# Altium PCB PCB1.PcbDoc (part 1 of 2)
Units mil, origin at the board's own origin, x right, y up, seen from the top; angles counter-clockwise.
Board outline 3937.01 x 3937.01 mil, 2 copper layers (Top Layer, Bottom Layer), stack 65.792 mil thick; 127 components, 100 nets, 530 pads, 138 vias.
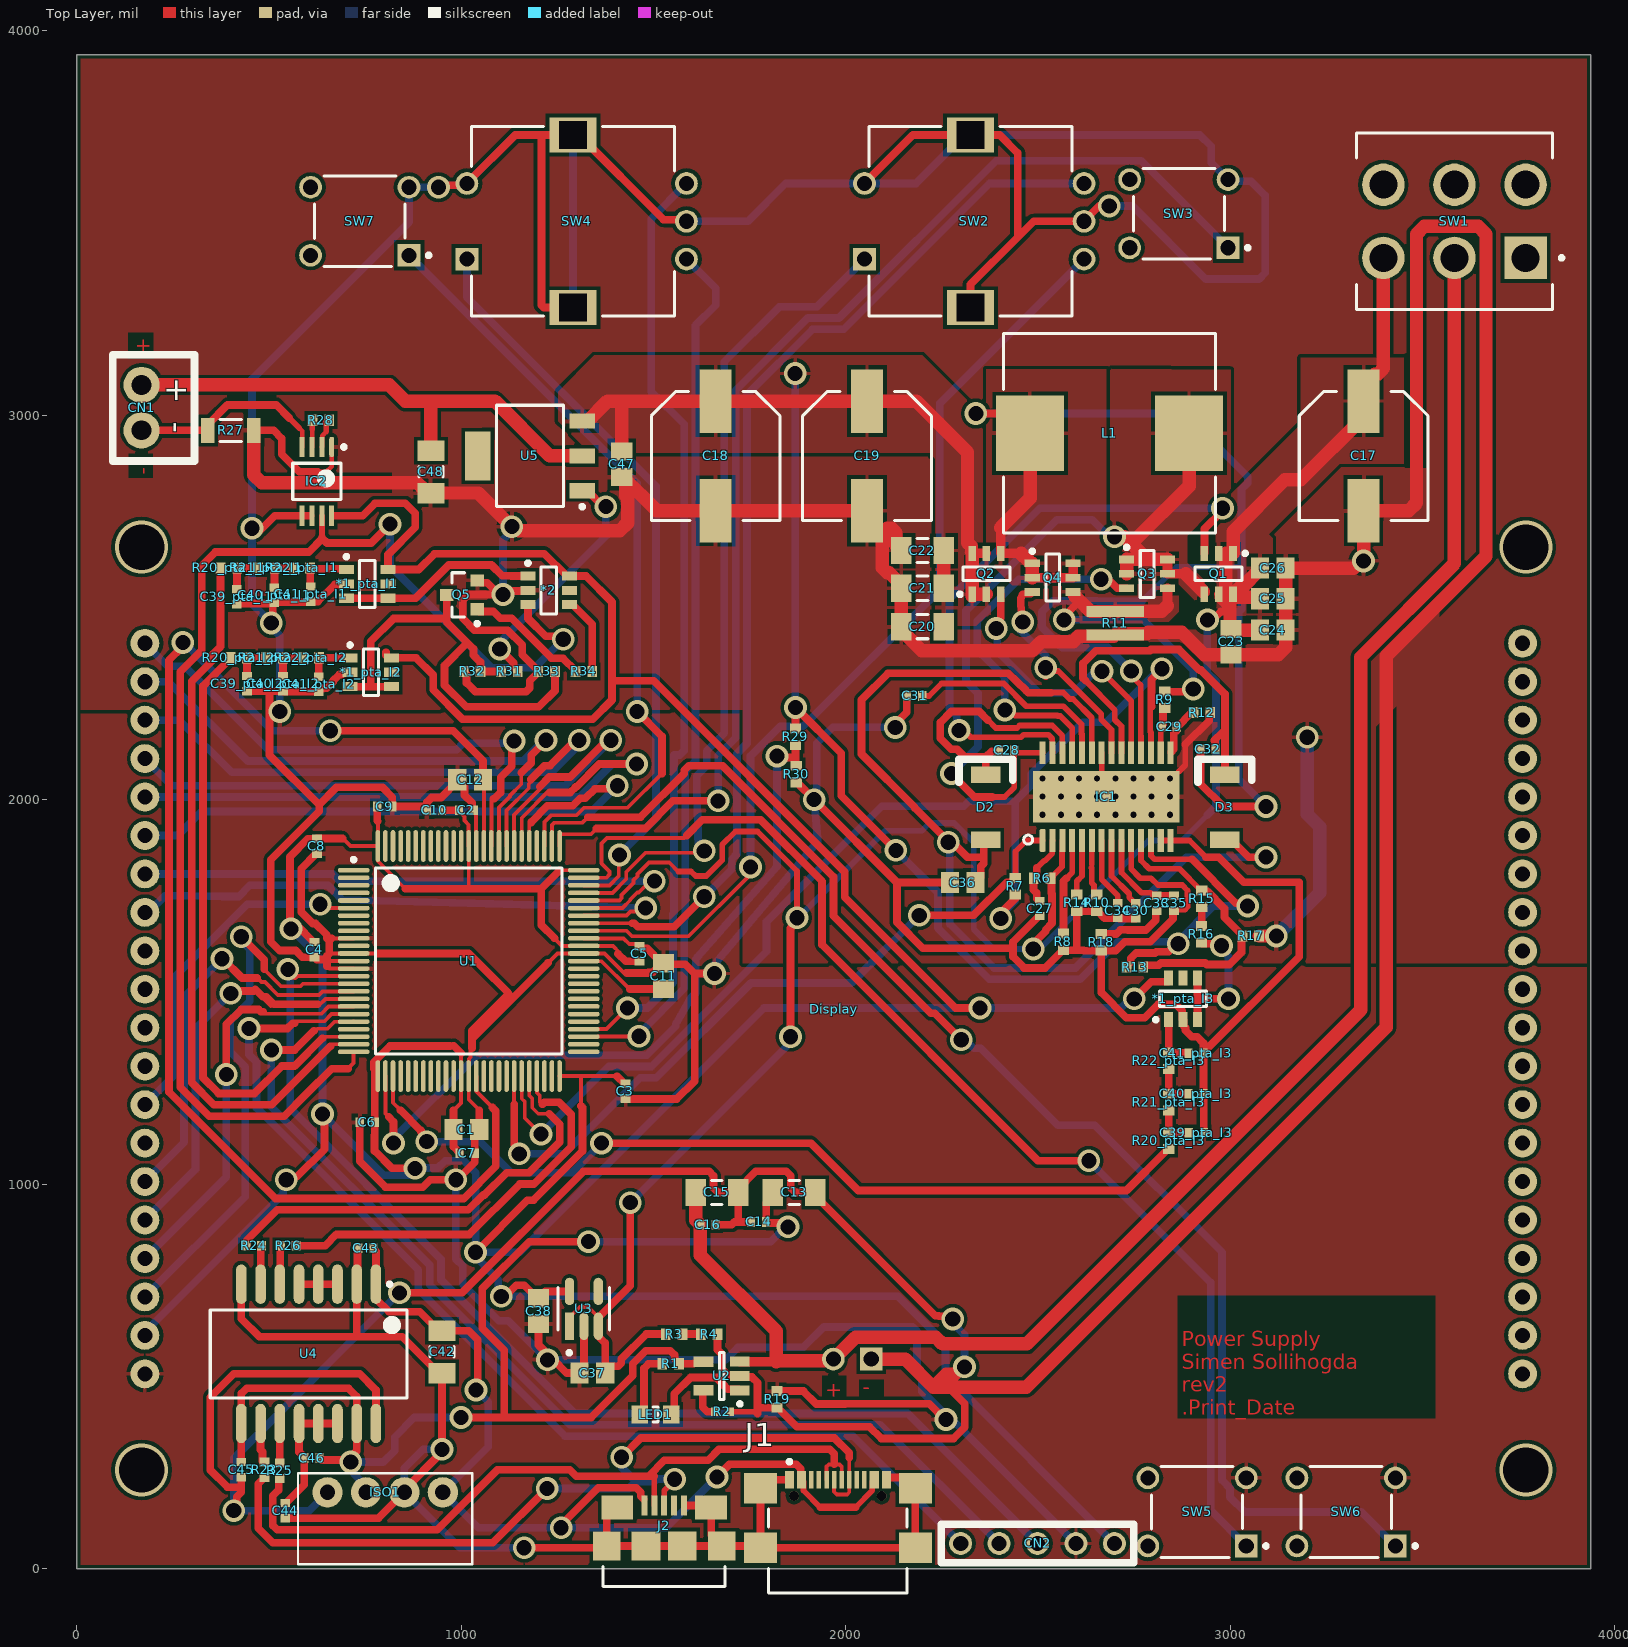
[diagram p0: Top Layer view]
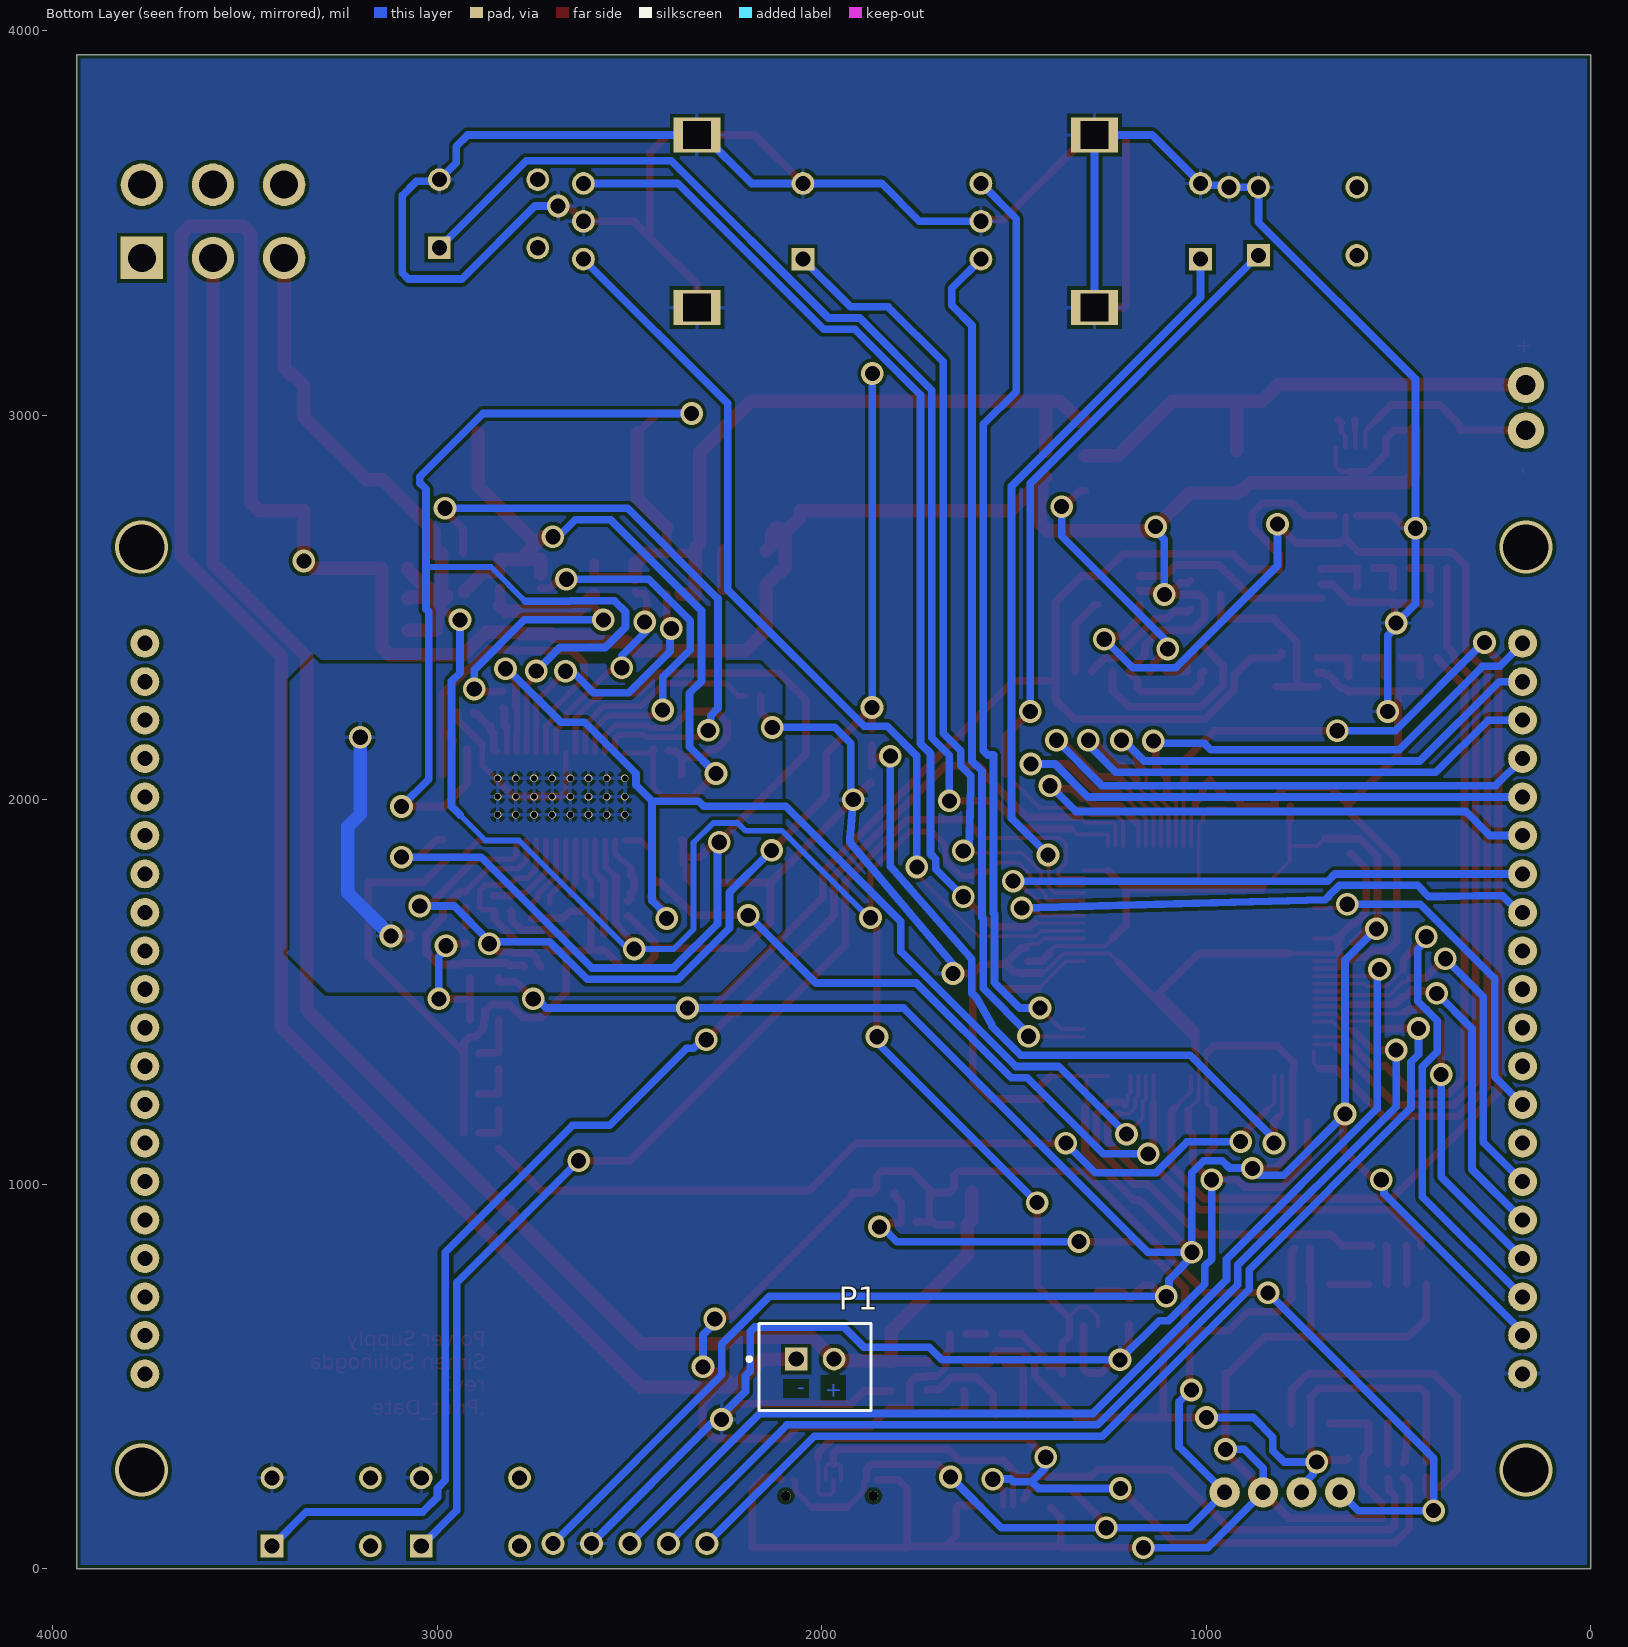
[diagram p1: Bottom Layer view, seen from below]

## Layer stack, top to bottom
Top Solder: solder mask 0.4, Solder Resist, Dk 3.5
Top Layer: signal copper 1.4
Dielectric 1: dielectric 62.9921, FR-4, Dk 4.8
Bottom Layer: signal copper 1.4
Bottom Solder: solder mask 0.4, Solder Resist, Dk 3.5

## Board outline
0,0 3937.01,0 3937.01,3937.01 0,3937.01

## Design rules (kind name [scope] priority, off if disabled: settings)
BoardOutlineClearance [(OnLayer('Bottom Layer') OR OnLayer('Top Layer') ) and not InAnyComponent] p1: gap=10 ignorepadtopadclearanceinfootprint=FALSE except(0: Arc-SplitContinuation Track-SplitContinuation SMDPad-SplitContinuation THPad-SplitContinuation Via-SplitContinuation Fill-SplitContinuation Poly-SplitContinuation Region-SplitContinuation Text-SplitContinuation; 39.37: Track-OutlineEdge SMDPad-OutlineEdge THPad-OutlineEdge Via-OutlineEdge; 118.11: Text-OutlineEdge)
Clearance Clearance_2 [InComponent('u1') or InComponent('J1') vs IsWire] p1: gap=6 ignorepadtopadclearanceinfootprint=FALSE
Clearance Clearance_1 [IsPad vs IsPad] p2: gap=6 ignorepadtopadclearanceinfootprint=FALSE
Clearance [All] p3: gap=9.5 ignorepadtopadclearanceinfootprint=FALSE
HoleSize HoleSize_1 [InComponent('IC1') or InComponent('J1')] p1: absolutevalues=TRUE maxlimit=100 minlimit=11.81 maxpercent=80.000 minpercent=20.000
HoleSize [All] p2: absolutevalues=TRUE maxlimit=2362.2 minlimit=31.5 maxpercent=80.000 minpercent=20.000
MinimumSolderMaskSliver [not InAnyComponent] p1: minsoldermaskwidth=4
PolygonConnect [All] p1: connectstyle=Relief reliefconductorwidth=10 reliefentries=4 polygonreliefangle="90 Angle" airgapwidth=10
RoutingVias [All] p1: holewidth=15.75 width=22.05 viastyle="Through Hole" minholewidth=15.75 minwidth=22.05 maxholewidth=39.37 maxwidth=78.74
SilkToSilkClearance [All] p1 off: silktosilkclearance=10
SilkToSolderMaskClearance [IsPad] p1: minsilkscreentomaskgap=0 clearancetoexposedcopper=FALSE
SolderMaskExpansion [All] p1: expansion=4 istentingtop=FALSE
Width [All] p1: maxlimit=100 minlimit=8 preferedwidth=20
26 further rules are at their usual default settings.

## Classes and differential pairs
component class U_programmer: CN2
component class U_linear_regulator: *2 C47 C48 Q5 R31 R32 R33 R34 U5
component class U_Display: Display
component class pta_I1: *1_pta_I1 C39_pta_I1 C40_pta_I1 C41_pta_I1 R20_pta_I1 R21_pta_I1 R22_pta_I1
component class U_Driver: CN1 R29 R30
component class U_mcu: C1 C2 C3 C4 C5 C6 C7 C8 C9 C10 C11 C12 U1
component class U_knobs: SW2 SW3 SW4 SW5 SW6 SW7
component class U_current_sense: IC2 R27 R28
component class U_Booster: C17 C18 C19 C20 C21 C22 C23 C24 C25 C26 C27 C28 C29 C30 C31 C32 C33 C34 C35 C36 D2 D3 IC1 L1 Q1 Q2 Q3 Q4 R6 R7 R8 R8_U_Booster R9 R10 R11 R12 R13 R14 R15 R16 R17 R18
component class pta_I3: *1_pta_I3 C39_pta_I3 C40_pta_I3 C41_pta_I3 R20_pta_I3 R21_pta_I3 R22_pta_I3
component class pta_I2: *1_pta_I2 C39_pta_I2 C40_pta_I2 C41_pta_I2 R20_pta_I2 R21_pta_I2 R22_pta_I2
component class U_usb_isolator: C42 C43 C44 C45 C46 ISO1 R23 R24 R25 R26 U4
component class U_usb: J1 J2
component class LDO: C37 C38 R19 U3
channel class pwm_to_analog: pta_I3 pta_V
component class Battery: C13 C14 C15 C16 LED1 P1 R1 R2 R3 R4 SW1 U2

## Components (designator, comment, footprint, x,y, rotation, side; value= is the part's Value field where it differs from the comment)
*1_pta_I1 "LMV341IDBVR" SOT95P280X145-6N 755.47,2561.02 r0 top (schematic designator *1)
*1_pta_I2 "LMV341IDBVR" SOT95P280X145-6N 764.76,2331.24 r0 top (schematic designator *1)
*1_pta_I3 "LMV341IDBVR" SOT95P280X145-6N 2876.97,1481.95 r90 top (schematic designator *1)
*2 "LMV341IDBVR" SOT95P280X145-6N 1227.51,2544.29 r0 top
C1 "CL21B105KBFNNNG" CAP0805 1013.34,1141.73 r180 top
C2 "GRM155R71H104ME14D" cap0402 1013.34,1972.14 r180 top value=100nF
C3 "GRM155R71H104ME14D" cap0402 1426.87,1241.36 r90 top value=100nF
C4 "GRM155R71H104ME14D" cap0402 618.28,1609.7 r90 top value=100nF
C5 "GRM155R71H104ME14D" cap0402 1463.63,1599.08 r270 top value=100nF
C6 "GRM155R71H104ME14D" cap0402 755.47,1160.91 r0 top value=100nF
C7 "GRM155R71H104ME14D" cap0402 1015.07,1080.18 r180 top value=100nF
C8 "GRM155R71H104ME14D" cap0402 624.68,1879.04 r90 top value=100nF
C9 "GRM155R71H104ME14D" cap0402 801.12,1981.98 r180 top value=100nF
C10 "GRM155R71H104ME14D" cap0402 930,1972.14 r0 top value=100nF
C11 "CL21B105KBFNNNG" CAP0805 1525.69,1540.81 r270 top
C12 "CL21B105KBFNNNG" CAP0805 1023.08,2051.48 r0 top
C13 "CL31A106MBHNNNE" Chip2PinSM127P600-8N#1 1865.55,978.41 r180 top
C14 "GRM155R71H104ME14D" cap0402 1773.03,901.64 r0 top value=100nF
C15 "CL31A106MBHNNNE" Chip2PinSM127P600-8N#1 1664.76,978.41 r180 top
C16 "GRM155R71H104ME14D" cap0402 1641.14,894.75 r180 top value=100nF
C17 "EEE-1HA101UP" CAPAE9983X102N 3346.42,2893.7 r270 top
C18 "EEE-1HA101UP" CAPAE9983X102N 1661.38,2893.7 r270 top
C19 "EEE-1HA101UP" CAPAE9983X102N 2055.08,2893.7 r270 top
C20 "CL31A106MBHNNNE" Chip2PinSM127P600-8N#1 2199.22,2449.8 r0 top
C21 "CL31A106MBHNNNE" Chip2PinSM127P600-8N#1 2199.22,2549.7 r0 top
C22 "CL31A106MBHNNNE" Chip2PinSM127P600-8N#1 2199.22,2647.64 r0 top
C23 "CL21B105KBFNNNG" CAP0805 3001.98,2410.49 r90 top
C24 "CL21B105KBFNNNG" CAP0805 3110.24,2440.95 r180 top
C25 "CL21B105KBFNNNG" CAP0805 3110.24,2522.4 r180 top
C26 "CL21B105KBFNNNG" CAP0805 3110.24,2602.2 r180 top
C27 "GRM155R71H104ME14D" cap0402 2503.94,1716.79 r270 top value=100nF
C28 "GRM155R71H104ME14D" cap0402 2418.11,2128.67 r180 top value=100nF
C29 "885012005078" cap0402 2841.07,2189.86 r0 top
C30 "GRM155R71H104ME14D" cap0402 2753.66,1710.63 r90 top value=100nF
C31 "GRM155R71H104ME14D" cap0402 2178.92,2269.53 r0 top value=100nF
C32 "GRM155R71H104ME14D" cap0402 2941.79,2131.26 r0 top value=100nF
C33 "CC0402KRX7R9BB223" cap0402 2808.77,1730.32 r90 top
C34 "885012005080" cap0402 2707.22,1711.62 r90 top
C35 "885012005080" cap0402 2853.52,1730.32 r90 top
C36 "CL21B105KBFNNNG" CAP0805 2304.08,1784.45 r180 top
C37 "CL21B105KBFNNNG" CAP0805 1340.75,508.7 r0 top
C38 "CL21B105KBFNNNG" CAP0805 1200.79,669.88 r90 top
C39_pta_I1 "GRM155R71H104ME14D" cap0402 416.34,2527.56 r90 top value=100nF (schematic designator C39)
C39_pta_I2 "GRM155R71H104ME14D" cap0402 442.87,2301.71 r90 top value=100nF (schematic designator C39)
C39_pta_I3 "GRM155R71H104ME14D" cap0402 2911.47,1133.52 r180 top value=100nF (schematic designator C39)
C40_pta_I1 "GRM155R71H104ME14D" cap0402 513.78,2531.5 r90 top value=100nF (schematic designator C40)
C40_pta_I2 "GRM155R71H104ME14D" cap0402 536.42,2301.71 r90 top value=100nF (schematic designator C40)
C40_pta_I3 "GRM155R71H104ME14D" cap0402 2910.43,1234.9 r180 top value=100nF (schematic designator C40)
C41_pta_I1 "GRM155R71H104ME14D" cap0402 608.44,2534.45 r90 top value=100nF (schematic designator C41)
C41_pta_I2 "GRM155R71H104ME14D" cap0402 629.11,2299.86 r90 top value=100nF (schematic designator C41)
C41_pta_I3 "GRM155R71H104ME14D" cap0402 2910.43,1340.55 r180 top value=100nF (schematic designator C41)
C42 "CL31A106MBHNNNE" Chip2PinSM127P600-8N#1 949.88,563.82 r90 top
C43 "GRM155R71H104ME14D" cap0402 751.79,833.21 r0 top value=100nF
C44 "GRM155R71H104ME14D" cap0402 541.81,150.9 r270 top value=100nF
C45 "GRM155R71H104ME14D" cap0402 428.03,257.68 r90 top value=100nF
C46 "GRM155R71H104ME14D" cap0402 611.49,287.82 r0 top value=100nF
C47 "CL21B105KBFNNNG" CAP0805 1417.32,2872.05 r90 top
C48 "CL31A106MBHNNNE" Chip2PinSM127P600-8N#1 920.94,2852.36 r90 top
CN1 "BU-P6883" 6883-Footprint-1 168.5,3019.23 r270 top
CN2 "PPPC051LFBN-RC" PR20203VBNN-Footprint-1 2498.43,65.55 r90 top locked
D2 "PMEG60T10ELPX" SODFL470X110-2N 2364.09,1980.32 r270 top
D3 "PMEG60T10ELPX" SODFL470X110-2N 2985.88,1980.32 r270 top
Display "2050" 2050-Footprint-1 1968.5,1456.69 r90 top locked
IC1 "LM5175-Q1" HTSSOP-28 2677.16,2007.87 r90 top
IC2 "AD8236" 8-MSOP 624.68,2827.46 r270 top
ISO1 "RFM-0505S" RFM-0505S-Footprint-1 801.91,198.62 r180 top locked
J1 "USB4110-GF-A" FP-USB4110-GF-A-MFG 1979.33,86.76 r0 top locked
J2 "10118192-0001LF" FCI-10118192-0001LF-5_V 1527.56,59.06 r0 top locked
L1 "7443551730" INDP130128X65N 2685.78,2952.76 r180 top
LED1 "150080BS75000" 0805_A 1505.02,400.83 r180 top
P1 "B2B-XH-A(LF)(SN)" JST-B2B-XH-A_V 2016.73,545.22 r180 bottom
Q1 "PMN55ENEX" TSOP95P280X110-6N_PMN55ENE 2969.48,2587.1 r270 top
Q2 "PMN55ENEX" TSOP95P280X110-6N_PMN55ENE 2365.61,2587.09 r90 top
Q3 "PMN55ENEX" TSOP95P280X110-6N_PMN55ENE 2783.35,2587.1 r0 top
Q4 "PMN55ENEX" TSOP95P280X110-6N_PMN55ENE 2537.98,2577.25 r0 top
Q5 "MMBTA42LT1G" ONSC-SOT-23-3-318-08_V 1001.77,2532.48 r180 top
R1 "RC0402FR-071KL" SMD_0402(1005)_M 1544.29,532.63 r0 top value=1k
R2 "RC0402FR-072K2L" RESC1005X40X25NL05T10 1679.14,407.84 r180 top value=2.2k
R3 "RC0402FR-0710KL" SMD_0402(1005)_M 1553.15,610.09 r180 top value=10k
R4 "RC0402FR-0710KL" SMD_0402(1005)_M 1644.69,610.09 r180 top value=10k
R6 "RC0402FR-0710RL" SMD_0402(1005)_M 2510.24,1795.28 r0 top value=10
R7 "RC0402FR-0710KL" SMD_0402(1005)_M 2440.95,1774.61 r90 top value=10k
R8 "RC0402FR-0749K9L" SMD_0402(1005)_M 2565.93,1629.78 r90 top value=49.9k
R9 "RC0402FR-07100RL" SMD_0402(1005)_M 2829.26,2259.69 r90 top value=100
R10 "RC0402FR-07100KL" SMD_0402(1005)_M 2652.96,1731.35 r90 top value=100k
R11 "CFG0612-FX-R010ELF" Chip2PinSM127P600-8N#2 2700.67,2458.72 r90 top
R12 "RC0402FR-07100RL" SMD_0402(1005)_M 2925.84,2226.38 r0 top value=100
R13 "RC0402FR-07100KL" SMD_0402(1005)_M 2751.69,1564.62 r180 top value=100k
R14 "RC0402FR-070RL" SMD_0402(1005)_M 2600.8,1731.3 r90 top value=0
R15 "RC0402FR-0710KL" SMD_0402(1005)_M 2925.84,1742.13 r270 top value=10k
R16 "RC0402FR-0710KL" SMD_0402(1005)_M 2924.86,1649.61 r270 top value=10k
R17 "RC0402FR-0710KL" SMD_0402(1005)_M 3053.15,1645.35 r180 top value=10k
R18 "RC0402FR-0710KL" SMD_0402(1005)_M 2664.01,1628.94 r90 top value=10k
R19 "RC0402FR-070RL" SMD_0402(1005)_M 1821.06,440.2 r90 top value=0
R20_pta_I1 "RC0402FR-0710KL" SMD_0402(1005)_M 395.67,2602.36 r0 top value=10k (schematic designator R20)
R20_pta_I2 "RC0402FR-0710KL" SMD_0402(1005)_M 421.22,2368.64 r0 top value=10k (schematic designator R20)
R20_pta_I3 "RC0402FR-0710KL" SMD_0402(1005)_M 2839.57,1112.85 r90 top value=10k (schematic designator R20)
R21_pta_I1 "RC0402FR-0710KL" SMD_0402(1005)_M 493.11,2602.36 r0 top value=10k (schematic designator R21)
R21_pta_I2 "RC0402FR-0710KL" SMD_0402(1005)_M 514.77,2369.19 r0 top value=10k (schematic designator R21)
R21_pta_I3 "RC0402FR-0710KL" SMD_0402(1005)_M 2839.57,1213.25 r90 top value=10k (schematic designator R21)
R22_pta_I1 "RC0402FR-0710KL" SMD_0402(1005)_M 584.82,2602.36 r0 top value=10k (schematic designator R22)
R22_pta_I2 "RC0402FR-0710KL" SMD_0402(1005)_M 608.44,2369.19 r0 top value=10k (schematic designator R22)
R22_pta_I3 "RC0402FR-0710KL" SMD_0402(1005)_M 2839.57,1321.32 r90 top value=10k (schematic designator R22)
R23 "RC0402FR-0724RL" RESC1005X40X25ML05T10 487.77,256.69 r90 top
R24 "RC0402FR-0724RL" RESC1005X40X25ML05T10 460.51,839.77 r180 top
R25 "RC0402FR-0724RL" RESC1005X40X25ML05T10 528.03,254.72 r90 top
R26 "RC0402FR-0724RL" RESC1005X40X25ML05T10 549.68,839.77 r0 top
R27 "ERJ-8BSFR10V" Chip2PinSM127P600-8N#3 400.45,2960.18 r0 top value=0.1
R28 "RC0402FR-074K42L" SMD_0402(1005)_M 635.04,2987.01 r0 top value=4.42k
R29 "RC0402FR-0710KL" SMD_0402(1005)_M 1869.05,2163.12 r90 top value=10k
R30 "RC0402FR-0710KL" SMD_0402(1005)_M 1871.01,2066.25 r90 top value=10k
R31 "RC0402FR-071KL" SMD_0402(1005)_M 1125,2333.21 r0 top value=1k
R32 "RC0402FR-071KL" SMD_0402(1005)_M 1028.1,2333.21 r0 top value=1k
R33 "RC0402FR-071KL" SMD_0402(1005)_M 1221.9,2333.21 r0 top value=1k
R34 "RC0402FR-071KL" SMD_0402(1005)_M 1318.8,2333.21 r0 top value=1k
SW1 "100DP1T2B3M2QEH" FP-100DP1T2B3M2QEH-MFG 3582.68,3503.94 r180 top
SW2 "PEC11R-4215F-S0024" BOUR-PEC11R-4XXXF-SXXXX_V 2324.14,3503.94 r90 top
SW3 "PTS645SM43SMTR92LFS" ITT-PTS645S-4_V 2866.13,3523.63 r180 top
SW4 "PEC11R-4215F-S0024" BOUR-PEC11R-4XXXF-SXXXX_V 1290.28,3503.94 r90 top
SW5 "PTS645SM43SMTR92LFS" ITT-PTS645S-4_V 2913.39,147.64 r180 top
SW6 "PTS645SM43SMTR92LFS" ITT-PTS645S-4_V 3301.18,147.64 r180 top
SW7 "PTS645SM43SMTR92LFS" ITT-PTS645S-4_V 736.05,3503.94 r180 top
U1 "CY8C5867AXI-LP024" CYP-AX100_M 1019.25,1580.18 r0 top
U2 "MCP73832T-2ACI/OT" SOT-23-OT5_M 1677.17,501.23 r180 top
U3 "TLV74333PDBVR" FP-DBV0005A-IPC_A 1318.9,675.79 r90 top
U4 "ADUM4160BRIZ-RL" ADI-RI-16-1_M 603.03,558.65 r270 top
U5 "LT3080EST#TRPBF" LT-ST-3-SOT-223_M 1178.59,2893.7 r180 top

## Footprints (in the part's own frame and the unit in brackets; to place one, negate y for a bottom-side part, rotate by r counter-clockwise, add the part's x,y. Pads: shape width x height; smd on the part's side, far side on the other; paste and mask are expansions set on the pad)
8-MSOP [mm] "TSOP, 8-Leads, Body 3.00x3.00mm, Pitch 0.65mm, IPC Medium Density"
  oval 1.35x0.33 smd: 1(-2.275,0.975)
  rect 1.35x0.33 smd: 2(-2.275,0.325) 3(-2.275,-0.325) 4(-2.275,-0.975) 5(2.275,-0.975) 6(2.275,-0.325) 7(2.275,0.325) 8(2.275,0.975)
  silkscreen extent -2.4,-1.6 1.2,1.9, body extent -2.45,-1.6 2.45,1.6, height 0.95
0805_A [mm] "Chip LED, 2-Leads, Body 2.0x1.3mm, IPC Medium Density"
  rect 1.1x1.2 smd: 1(-1.05,0) 2(1.05,0)
  silkscreen extent -0.15,-0.5 0.15,0.5, body extent -1,-0.62 1,0.63, height 0.68
2050-Footprint-1 [mm]
  round 1.905 hole 1: 1(24.13,-45.5) 2(21.59,-45.5) 3(19.05,-45.5) 4(16.51,-45.5) 5(13.97,-45.5) 6(11.43,-45.5) 7(8.89,-45.5) 8(6.35,-45.5) 9(3.81,-45.5) 10(1.27,-45.5) 11(-1.27,-45.5) 12(-3.81,-45.5) 13(-6.35,-45.5) 14(-8.89,-45.5) 15(-11.43,-45.5) 16(-13.97,-45.5) 17(-16.51,-45.5) 18(-19.05,-45.5) 19(-21.59,-45.5) 20(-24.13,-45.5) 21(-24.13,45.5) 22(-21.59,45.5) 23(-19.05,45.5) 24(-16.51,45.5) 25(-13.97,45.5) 26(-11.43,45.5) 27(-8.89,45.5) 28(-6.35,45.5) 29(-3.81,45.5) 30(-1.27,45.5) 31(1.27,45.5) 32(3.81,45.5) 33(6.35,45.5) 34(8.89,45.5) 35(11.43,45.5) 36(13.97,45.5) 37(16.51,45.5) 38(19.05,45.5) 39(21.59,45.5) 40(24.13,45.5)
  body extent -35,-50 35,50, height 10
6883-Footprint-1 [mm]
  round 2.4 hole 1.3: 1(-1.5,0) 2(1.5,0)
  silkscreen extent -3.5,-1.9 3.53,3.5
ADI-RI-16-1_M [mm] "SOIC, 16-Leads, Body 12.8x7.5mm, Pitch 1.27mm, IPC Low Density"
  oval 2.6x0.7 smd: 1(-4.6,4.445) 2(-4.6,3.175) 3(-4.6,1.905) 4(-4.6,0.635) 5(-4.6,-0.635) 6(-4.6,-1.905) 7(-4.6,-3.175) 8(-4.6,-4.445) 9(4.6,-4.445) 10(4.6,-3.175) 11(4.6,-1.905) 12(4.6,-0.635) 13(4.6,0.635) 14(4.6,1.905) 15(4.6,3.175) 16(4.6,4.445)
  silkscreen extent -4.72,-6.5 2.9,6.5, body extent -3.8,-6.5 3.8,6.5, height 2.65
BOUR-PEC11R-4XXXF-SXXXX_V [mm] "THD, 5-Leads, Body 12.5x13.4mm"
  rect 1.5x1.5 hole 1: 1(-2.5,7)
  round 1.5 hole 1: 2(2.5,7) 3(2.5,-7.5) 4(0,-7.5) 5(-2.5,-7.5)
  rect 2.3x3.1 hole 1.8 square: 6(-5.7,0) 7(5.7,0)
  silkscreen extent -6.25,-6.7 6.25,6.7, body extent -7,-7.7 7,7.2, height 21.61
cap0402 [mm] "0402 footprint for capasitors"
  rect 0.54x0.64 smd: 1(-0.5,0) 2(0.5,0)
  body extent -0.5,-0.25 0.5,0.25, height 0.5
CAP0805 [mm] "0804 smd capasitor"
  rect 1.2x1.4 smd: 1(-0.85,0) 2(0.85,0)
  body extent -1.05,-0.63 1.05,0.63, height 1.35
CAPAE9983X102N [mm] "Aluminum Electrolytic Capacitor, Body 8.30x8.30x10.20mm, IPC Medium Density"
  rect 4.2x2.1 smd: 1(-3.625,0) 2(3.625,0)
  silkscreen extent -4.25,-4.25 4.25,4.25, body extent -4.95,-4.25 4.95,4.25, height 10.2
Chip2PinSM127P600-8N#1 [mm] "1206 ceramic capasitor"
  rect 1.35x1.8 smd: 1(-1.4,0) 2(1.4,0)
  silkscreen extent -0.35,-0.8 0.35,0.8, body extent -1.7,-0.87 1.7,0.87, height 1.6
Chip2PinSM127P600-8N#2 [mm] "1206 flipped sens resitor"
  rect 0.7x3.8 smd: 1(-0.775,0) 2(0.775,0)
  body extent -0.8,-1.7 0.8,1.7, height 0.7
Chip2PinSM127P600-8N#3 [mm]
  rect 0.9x1.65 smd: 1(-1.525,0) 2(1.525,0)
  silkscreen extent -0.7,-0.73 0.7,0.73, body extent -1.6,-0.8 1.6,0.8, height 0.5
CYP-AX100_M [mm] "QFN, 100-Leads, Body 14x14mm, Pitch 0.5mm, IPC Low Density"
  oval 2.1x0.3 smd mask+0.05: 1(-7.6,6) 2(-7.6,5.5) 3(-7.6,5) 4(-7.6,4.5) 5(-7.6,4) 6(-7.6,3.5) 7(-7.6,3) 8(-7.6,2.5) 9(-7.6,2) 10(-7.6,1.5) 11(-7.6,1) 12(-7.6,0.5) 13(-7.6,0) 14(-7.6,-0.5) 15(-7.6,-1) 16(-7.6,-1.5) 17(-7.6,-2) 18(-7.6,-2.5) 19(-7.6,-3) 20(-7.6,-3.5) 21(-7.6,-4) 22(-7.6,-4.5) 23(-7.6,-5) 24(-7.6,-5.5) 25(-7.6,-6) 51(7.6,-6) 52(7.6,-5.5) 53(7.6,-5) 54(7.6,-4.5) 55(7.6,-4) 56(7.6,-3.5) 57(7.6,-3) 58(7.6,-2.5) 59(7.6,-2) 60(7.6,-1.5) 61(7.6,-1) 62(7.6,-0.5) 63(7.6,0) 64(7.6,0.5) 65(7.6,1) 66(7.6,1.5) 67(7.6,2) 68(7.6,2.5) 69(7.6,3) 70(7.6,3.5) 71(7.6,4) 72(7.6,4.5) 73(7.6,5) 74(7.6,5.5) 75(7.6,6)
  oval 0.3x2.1 smd mask+0.05: 26(-6,-7.6) 27(-5.5,-7.6) 28(-5,-7.6) 29(-4.5,-7.6) 30(-4,-7.6) 31(-3.5,-7.6) 32(-3,-7.6) 33(-2.5,-7.6) 34(-2,-7.6) 35(-1.5,-7.6) 36(-1,-7.6) 37(-0.5,-7.6) 38(0,-7.6) 39(0.5,-7.6) 40(1,-7.6) 41(1.5,-7.6) 42(2,-7.6) 43(2.5,-7.6) 44(3,-7.6) 45(3.5,-7.6) 46(4,-7.6) 47(4.5,-7.6) 48(5,-7.6) 49(5.5,-7.6) 50(6,-7.6) 76(6,7.6) 77(5.5,7.6) 78(5,7.6) 79(4.5,7.6) 80(4,7.6) 81(3.5,7.6) 82(3,7.6) 83(2.5,7.6) 84(2,7.6) 85(1.5,7.6) 86(1,7.6) 87(0.5,7.6) 88(0,7.6) 89(-0.5,7.6) 90(-1,7.6) 91(-1.5,7.6) 92(-2,7.6) 93(-2.5,7.6) 94(-3,7.6) 95(-3.5,7.6) 96(-4,7.6) 97(-4.5,7.6) 98(-5,7.6) 99(-5.5,7.6) 100(-6,7.6)
  silkscreen extent -7.72,-6.15 6.15,6.82, body extent -7,-7 7,7, height 1.6
FCI-10118192-0001LF-5_V [mm] "SMD, 5-Leads, Body 8.05x5.77mm, Pitch 0.65mm"
  rect 0.4x1.35 smd mask+0.05: 1(-1.3,2.675) 2(-0.65,2.675) 3(0,2.675) 4(0.65,2.675) 5(1.3,2.675)
  rect 2.1x1.6 smd: 6(-3.1,2.55) 7(3.1,2.55)
  rect 1.8x1.9 smd: 8(-3.8,0) 9(3.8,0)
  rect 1.9x1.9 smd: 10(-1.2,0) 11(1.2,0)
  silkscreen extent -4.03,-2.67 4.03,-1.35, body extent -4.03,-2.67 4.03,3.1, height 2.7
FP-100DP1T2B3M2QEH-MFG [mm]
  rect 2.8x2.8 hole 1.85 paste-1000 mask+0: 1(-4.7,2.415)
  round 2.8 hole 1.85 paste-1000 mask+0: 2(0,2.415) 3(4.7,2.415) 4(-4.7,-2.415) 5(0,-2.415) 6(4.7,-2.415)
  silkscreen extent -7.2,-5.84 6.48,5.84, body extent -6.58,-5.94 6.58,5.94, height 0.25
FP-DBV0005A-IPC_A [mm]
  rect 1.805x0.612 smd paste+0 mask+0: 1(-1.15,0.95)
  rrect100% 1.805x0.612 smd paste+0 mask+0: 2(-1.15,0) 3(-1.15,-0.95) 4(1.151,-0.95) 5(1.151,0.95)
  silkscreen extent -3.03,-1.7 1.4,1.7, body extent -2.55,-1.95 2.55,1.95, height 0.25
FP-USB4110-GF-A-MFG [mm]
  rect 2.18x2 smd paste+0 mask+0: 1(-5.11,3.105) 2(5.11,3.105) 3(-5.11,-0.825) 4(5.11,-0.825)
  rect 0.6x1.15 smd paste+0 mask+0: A1-B12(-3.2,3.68) A4-B9(-2.4,3.68) B1-A12(3.2,3.68) B4-A9(2.4,3.68)
  rect 0.3x1.15 smd paste+0 mask+0: A5(-1.25,3.68) A6(-0.25,3.68) A7(0.25,3.68) A8(1.25,3.68) B5(1.75,3.68) B6(0.75,3.68) B7(-0.75,3.68) B8(-1.75,3.68)
  round 0.65 hole 0.65 unplated paste-1000 mask+0: ""(-2.89,2.605) ""(2.89,2.605)
  silkscreen extent -4.57,-3.83 4.57,4.99, body extent -6.3,-3.92 6.3,4.36, height 0.25
HTSSOP-28 [mm]
  rrect50% 1.5x0.4 smd mask+0.05: 1(-2.9,4.2)
  rect 1.5x0.4 smd mask+0.05: 2(-2.9,3.55) 3(-2.9,2.9) 4(-2.9,2.25) 5(-2.9,1.6) 6(-2.9,0.95) 7(-2.9,0.3) 8(-2.9,-0.35) 9(-2.9,-1) 10(-2.9,-1.65) 11(-2.9,-2.3) 12(-2.9,-2.95) 13(-2.9,-3.6) 14(-2.9,-4.25) 15(2.9,-4.25) 16(2.9,-3.6) 17(2.9,-2.95) 18(2.9,-2.3) 19(2.9,-1.65) 20(2.9,-1) 21(2.9,-0.35) 22(2.9,0.3) 23(2.9,0.95) 24(2.9,1.6) 25(2.9,2.25) 26(2.9,2.9) 27(2.9,3.55) 28(2.9,4.2)
  rect 3.4x9.7 smd paste-100 mask+0.102: -(0,0)
  silkscreen extent -3.14,4.86 -2.55,5.46, body extent -3.2,-4.9 3.2,7.24, height 0.97
INDP130128X65N [mm] "Precision Wire Wound Inductor, 2-Leads, Body 13.00x12.75mm, IPC Medium Density"
  rect 4.5x5 smd: 1(-5.25,0) 2(5.25,0)
  silkscreen extent -7,-6.6 7,6.6, body extent -6.6,-6.38 6.6,6.38, height 6.6
ITT-PTS645S-4_V [mm] "TH, 4-Leads, Body 6x6mm"
  rect 1.5x1.5 hole 1: 1(-3.25,2.25)
  round 1.5 hole 1: 2(3.25,2.25) 3(-3.25,-2.25) 4(3.25,-2.25)
  silkscreen extent -4.68,-3 3,3, body extent -3,-3 3,3, height 4.4
JST-B2B-XH-A_V [mm] "Header, 2-Leads, Body 7.4x5.75mm, Pitch 2.5mm"
  rect 1.5x1.5 hole 1: 1(-1.25,0)
  round 1.5 hole 1: 2(1.25,0)
  silkscreen extent -4.47,-3.4 3.7,2.35, body extent -3.7,-3.4 3.7,2.35, height 7
LT-ST-3-SOT-223_M [mm] "SOT223, 4-Leads, Body 6.505x3.505mm, Pitch 2.3mm, IPC Low Density"
  rect 1.7x1 smd: 1(-3.45,2.3) 2(-3.45,0) 3(-3.45,-2.3)
  rect 1.7x3.25 smd: 4(3.45,0)
  silkscreen extent -3.58,-3.35 2.2,3.47, body extent -1.86,-3.35 1.86,3.35, height 1.8
ONSC-SOT-23-3-318-08_V [mm] "SOT23, 3-Leads, Body 2.92x1.3mm, Pitch 0.95mm"
  rect 0.9x0.8 smd: 1(-1,0.95) 2(-1,-0.95) 3(1,0)
  silkscreen extent -1.13,-1.46 0.65,2.02, body extent -0.65,-1.46 0.65,1.46, height 1.11
PR20203VBNN-Footprint-1 [mil]
  round 60 hole 40: 1(0,200) 2(0,100) 3(0,0)
  round 60 hole 39.37: 4(0,-100) 5(0,-200)
  silkscreen extent -50,-250 50,250, body extent -50,-260 300,260, height 335
RESC1005X40X25ML05T10 [mm] "Chip Resistor, 2-Leads, Body 1.00x0.50mm, IPC Low Density"
  rect 0.6x0.65 smd: 1(-0.508,0) 2(0.508,0)
  body extent -0.53,-0.27 0.53,0.28, height 0.4
RESC1005X40X25NL05T10 [mm] "Chip Resistor, 2-Leads, Body 1.00x0.50mm, IPC Medium Density"
  rect 0.5x0.55 smd: 1(-0.508,0) 2(0.508,0)
  body extent -0.53,-0.27 0.53,0.28, height 0.4
RFM-0505S-Footprint-1 [mm]
  round 2 hole 1: 1(-3.81,0) 2(-1.27,0) 3(1.27,0) 4(3.81,0)
  silkscreen extent -5.75,-1.25 5.75,4.75, body extent -5.8,-1.25 5.7,4.75, height 9.5
SMD_0402(1005)_M [mm] "Chip Resistor, Body 1.0x0.5mm, IPC Low Density"
  rect 0.65x0.75 smd: 1(-0.55,0) 2(0.55,0)
  body extent -0.52,-0.28 0.53,0.28, height 0.4
SODFL470X110-2N [mm] "SODFL, 2-Leads, Body 2.50x4.70mm, IPC Medium Density"
  rect 1.1x1.95 smd: 1(-2.15,0) 2(2.15,0)
  silkscreen extent -3.18,-1.78 -1.65,1.78, body extent -2.35,-1.35 2.35,1.35, height 1.1
SOT95P280X145-6N [mm] "SOT23, 6-Leads, Body 2.90x2.80mm, Pitch 0.95mm, IPC Medium Density"
  rect 1x0.6 smd: 1(-1.375,0.95) 2(-1.375,0) 3(-1.375,-0.95) 4(1.375,-0.95) 5(1.375,0) 6(1.375,0.95)
  silkscreen extent -1.5,-1.55 0.5,1.92, body extent -1.5,-1.53 1.5,1.53, height 1.45
SOT-23-OT5_M [mm] "SOT23, 5-Leads, Body 2.9x1.7mm, Pitch 0.95mm, Lead Span 2.8mm, IPC Low Density"
  rect 1.3x0.65 smd mask+0.05: 1(-1.2,0.95) 2(-1.2,0) 3(-1.2,-0.95)
  rect 1.3x0.7 smd: 4(1.2,-0.95) 5(1.2,0.95)
  silkscreen extent -1.33,-1.55 0.15,1.97, body extent -0.9,-1.55 0.9,1.55, height 1.45
TSOP95P280X110-6N_PMN55ENE [mm] "pin maping matches PMN55ENE- TSOP, 6-Leads, Body 2.90x1.50mm, Pitch 0.95mm, IPC Medium Density"
  rect 1x0.5 smd: 1(1.35,-0.95) 2(-1.35,0.95) 2(-1.35,0) 2(1.35,0.95) 2(1.35,0) 3(-1.35,-0.95)
  silkscreen extent -1.47,-1.55 0.45,1.88, body extent -1.38,-1.55 1.38,1.55, height 1.1

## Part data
*1_pta_I1 *1_pta_I2 *1_pta_I3 *2: library part CMP-ROOT-00000-1, "Single Rail-To-Rail Output CMOS Operational Amplifier with Shutdown 6-SOT-23 -40 to 125", Case/Package=SOT-23, Input Bias Current=200pA, Input Offset Voltage (Vos)=250uV, Max Frequency=1kHz, Max Operating Temperature=125°C, Max Supply Voltage=5.5V, Min Operating Temperature=-40°C, Min Supply Voltage=2.5V, Nominal Supply Current=170uA, Operating Supply Current=107uA, Output Current=32mA, Output Current per Channel=113mA, Package Quantity=1, Voltage Gain=116dB
C1 C11 C12 C23 C24 C25 C26 C36 C37 C38 C47: library part CMP-0001-00012-4, "SAMSUNG ELECTRO-MECHANICS - CL21B105KBFNNNG - MLCC CAPACITORS", Capacitance=1µF, Capacitor Type=Ceramic, Case Code (Imperial)=0805, Case Code (Metric)=2012, Dielectric=X7R, Max Operating Temperature=125°C, Min Operating Temperature=-55°C, Package Quantity=3000, Tolerance=10%, Voltage=50V
C2 C3 C4 C5 C6 C7 C8 C9 C10 C14 C16 C27 C28 C30 C31 C32 C39_pta_I1 C39_pta_I2 C39_pta_I3 C40_pta_I1 C40_pta_I2 C40_pta_I3 C41_pta_I1 C41_pta_I2 C41_pta_I3 C43 C44 C45 C46: library part CMP-0001-00001-8, "0402 0.1 uF 50 V ±20% Tolerance X7R SMT Monolithic Ceramic Chip Capacitor", Capacitance=100nF, Capacitor Type=Ceramic, Case/Package=0402, Max Operating Temperature=125°C, Min Operating Temperature=-55°C, Tolerance=20%, Voltage Rating=50V
C13 C15 C20 C21 C22 C42 C48: library part CMP-0001-00015-2, "CAP CER 10UF 50V X5R 1206", Capacitance=10µF, Capacitor Type=Ceramic, Case Code (Imperial)=1206, Case Code (Metric)=3216, Dielectric=X5R, Max Operating Temperature=85°C, Min Operating Temperature=-55°C, Tolerance=20%, Voltage Rating=50V
C17 C18 C19: library part CMP-0001-00014-2, "Cap Aluminum 100uF 50V 20% (8 X 10.2mm) SMD 200mA 2000 hr 85C T/R", Capacitance=100µF, Capacitor Type=Ceramic, Case/Package=Radial, Max Operating Temperature=85°C, Min Operating Temperature=-40°C, Package Quantity=1, Ripple Current=200mA, Tolerance=20%, Voltage Rating=50V
C29: library part CMP-0001-00009-6, "CAP CER 47PF 100V C0G/NP0 0402", Capacitance=47pF, Capacitor Type=Ceramic, Case Code (Imperial)=0402, Case Code (Metric)=1005, Max Operating Temperature=125°C, Min Operating Temperature=-55°C, Tolerance=5%, Voltage Rating=100V
C33: library part CMP-0001-00011-3, "Multilayer Ceramic Capacitors MLCC - SMD/SMT 22K pF 10% 50 Volts", Capacitance=22nF, Capacitor Type=Ceramic, Case Code (Imperial)=0402, Case Code (Metric)=1005, Dielectric=X7R, Max Operating Temperature=125°C, Min Operating Temperature=-55°C, Package Quantity=10000, Tolerance=10%, Voltage Rating=50V
C34 C35: library part CMP-0001-00010-3, "Cap, Mlcc, C0g, 100Pf, 100V, 0402", Capacitance=100pF, Capacitor Type=Ceramic, Case Code (Imperial)=0402, Case Code (Metric)=1005, Max Operating Temperature=125°C, Min Operating Temperature=-55°C, Tolerance=5%, Voltage Rating=100V
CN1: library part CMP-ROOT-00006-6, "CONN BIND POST DL FLUTD BLK/RED", Color=Black,Red
CN2: library part CMP-ROOT-00017-8, "CONN HDR 5POS 0.1 GOLD PCB", Color=Black, Package Quantity=1000
D2 D3: library part CMP-ROOT-00002-1, "Diode Schottky 60V 1A Surface Mount CFP5", Case/Package=SMA, Operating Temperature - Junction="175°C (Max)", Package / Case=SOD-128, Voltage - Forward (Vf) (Max) @ If="590mV @ 1A"
Display: library part CMP-ROOT-00015-3, "3.5\" TFT 320X480 TOUCHSCREEN", Case/Package=pcb
IC1: library part CMP-006-0002-14, "IC REG CTRLR BUCK-BOOST 28HTSSOP", Max Operating Temperature=125°C, Max Supply Voltage=42V, Min Operating Temperature=-40°C, Min Supply Voltage=3.5V, Quiescent Current=1.65mA, Switching Frequency=600kHz
IC2: library part CMP-006-0000-5, "IC OPAMP INSTR 23KHZ RRO 8MSOP", Case/Package=MSOP, Input Bias Current=10pA, Input Offset Voltage (Vos)=3.5mV, Input Resistance=440GR, Max Operating Temperature=125°C, Max Supply Voltage=5.5V, Min Operating Temperature=-40°C, Min Supply Voltage=1.8V, Operating Supply Current=40uA, Output Current per Channel=6mA, Package Quantity=1, Power Supply Rejection Ratio (PSRR)=130dB, Voltage Gain=46.02dB
ISO1: library part CMP-ROOT-00011-2, "RECOM POWER - RFM-0505S - Isolated Board Mount DC/DC Converter, ITE & General, 1 Output, 1 W, 5 V, 200 mA", Case/Package=dip, Max Output Voltage=5V
J1: library part CMP-ROOT-00018-1, "Conn Usb 2.0 Type-c R/a SMT"
J2: library part CMP-ROOT-00010-2, "CONN RCPT USB2.0 MICRO B SMD R/A", Color=Black, Current Rating=1.8A, Flammability Rating="UL94 V-0", Insulation Resistance=1GR, Max Operating Temperature=85°C, Max Voltage Rating (AC)=100V, Min Operating Temperature=-55°C, Package Quantity=1400
L1: library part CMP-ROOT-00003-1, "WURTH ELEKTRONIK         7443551730             Surface Mount Power Inductor, WE-HCI Series, 7.3 H, 13 A, 12 A, Shielded, 5900 ohm", Case/Package=1365, Current Rating=13A, DC Resistance (DCR)=5.9mR, Inductance=7.3uH, Inductance Tolerance=20%, Max Operating Temperature=155°C, Min Operating Temperature=-40°C, Package Quantity=400, Saturation Current=12A, Self Resonant Frequency=28MHz, Series Resistance=5.9R, Test Frequency=100kHz
LED1: library part CMP-00002-1, "SMD LED blue 3.5 V 0805, 150080BS75000, Würth Elektronik", Case Code (Imperial)=0805, Case Code (Metric)=2012, Color=Blue, Forward Current=30mA, Forward Voltage=3.2V, Max Operating Temperature=85°C, Min Operating Temperature=-40°C, Package Quantity=4000, Test Current=20mA
P1: library part CMP-ROOT-00008-1, "Conn Shrouded Header (4 Sides) HDR 2 POS 2.5mm Solder ST Thru-Hole Box", Color=Natural, Contact Resistance=20mR, Current Rating=3A, Housing Color=White, Insulation Resistance=1GR, Max Operating Temperature=85°C, Max Voltage Rating (AC)=250V, Min Operating Temperature=-25°C
Q1 Q2 Q3 Q4: library part CMP-ROOT-00001-4, "MOSFET N-CH 60V 4.5A 6TSOP", Case/Package=TSOP, Continuous Drain Current (ID)=4.5A, Drain to Source Voltage (Vdss)=60V, Input Capacitance=646pF, Max Operating Temperature=150°C, Max Power Dissipation=6.25mW, Min Operating Temperature=-55°C
Q5: library part CMP-ROOT-00016-1, "Trans GP BJT NPN 300V 0.5A Automotive 3-Pin SOT-23 T/R", Case/Package=SOT-23-3, Collector Base Voltage (VCBO)=300V, Collector Emitter Saturation Voltage=500mV, Current Rating=500mA, Emitter Base Voltage (VEBO)=6V, Frequency=50MHz, Max Operating Temperature=150°C, Max Power Dissipation=225mW, Min Operating Temperature=-55°C, Package Quantity=1, Power Dissipation=300mW
R1 R31 R32 R33 R34: library part CMP-001-0000-7, "Surface Mount Chip Resistor, Thick Film, RC Series, 1 kohm, 62.5 mW, 1%, 50 V, 0402 [1005 Metric]", Case Code (Imperial)=0402, Case Code (Metric)=1005, Max Operating Temperature=155°C, Min Operating Temperature=-55°C, Power Rating=62.5mW, Resistance=1k, Temperature Coefficient=100ppm/°C, Tolerance=1%, Voltage Rating=50V
R2: library part CMP-001-0020-3, "RES SMD 2.2K OHM 1% 1/16W 0402", Case Code (Imperial)=0402, Case Code (Metric)=1005, Max Operating Temperature=155°C, Min Operating Temperature=-55°C, Power Rating=63mW, Resistance=2.2k, Temperature Coefficient=100ppm/°C, Tolerance=1%, Voltage Rating=50V
R3 R4 R7 R15 R16 R17 R18 R20_pta_I1 R20_pta_I2 R20_pta_I3 R21_pta_I1 R21_pta_I2 R21_pta_I3 R22_pta_I1 R22_pta_I2 R22_pta_I3 R29 R30: library part CMP-008-0005-9, "Surface Mount Thick Film Resistor, Rc Series, 10 Kohm, 62.5 Mw, - 1%, 50 V, 0402 [1005 Metric]", Case Code (Imperial)=0402, Case Code (Metric)=1005, Max Operating Temperature=155°C, Min Operating Temperature=-55°C, Power Rating=62.5mW, Resistance=10k, Temperature Coefficient=100ppm/°C, Tolerance=1%, Voltage Rating=50V
R6: library part CMP-0001-00007-3, "RES SMD 10 OHM 1% 1/16W 0402", Case Code (Imperial)=0402, Case Code (Metric)=1005, Max Operating Temperature=155°C, Min Operating Temperature=-55°C, Power Rating=63mW, Resistance=10, Temperature Coefficient=100ppm/°C, Tolerance=1%, Voltage Rating=50V
R8: library part CMP-0001-00013-2, "Res Thick Film 0402 49.9K Ohm 1% 0.063W(1/16W) ±100ppm/C Epoxy Pad SMD T/R", Case Code (Imperial)=0402, Case Code (Metric)=1005, Max Operating Temperature=155°C, Min Operating Temperature=-55°C, Power Rating=62.5mW, Resistance=49.9k, Temperature Coefficient=100ppm/°C, Tolerance=1%, Voltage Rating=50V
R9 R12: library part CMP-0001-00008-3, "YAGEO - RC0402FR-07100RL. - RES, THICK FILM, 100R, 1%, 0.0625W, 0402, REEL", Case Code (Imperial)=0402, Case Code (Metric)=1005, Max Operating Temperature=155°C, Min Operating Temperature=-55°C, Power Rating=62.5mW, Resistance=100, Temperature Coefficient=100ppm/°C, Tolerance=1%, Voltage Rating=50V
R10 R13: library part CMP-0001-00006-4, "Res General Purpose Thick Film 0402 100K Ohm 1% 1/16W ±100ppm/°C Molded SMD Paper T/R", Case Code (Imperial)=0402, Case Code (Metric)=1005, Max Operating Temperature=155°C, Max Power Dissipation=63mW, Min Operating Temperature=-55°C, Package Quantity=1, Resistance=100k, Temperature Coefficient=100ppm/°C, Tolerance=1%, Voltage Rating=50V
R11: library part CMP-0001-00016-1, "BOURNS JW MILLER - CFG0612-FX-R010ELF - SMD Current Sense Resistor, 0.01 ohm, CFG Series, 1206 Wide, 1 W, ± 1%, Metal Foil", Case/Package="Wide 1206 (3216 Metric), 0612", Resistance=10m
R14 R19: library part CMP-0001-00005-6, "Res Thick Film 0402 0 Ohm Molded SMD SMD Paper T/R", Case Code (Imperial)=0402, Case Code (Metric)=1005, Max Operating Temperature=155°C, Min Operating Temperature=-55°C, Power Rating=62.5mW, Resistance=0, Temperature Coefficient=200ppm/°C, Tolerance=1%, Voltage Rating=50V
R23 R24 R25 R26: library part CMP-0001-00017-2, "Thick Film Resistors 24 OHM 1%", Case Code (Imperial)=0402, Case Code (Metric)=1005, Max Operating Temperature=155°C, Max Power Dissipation=63mW, Min Operating Temperature=-55°C, Resistance=24, Temperature Coefficient=100ppm/°C, Tolerance=1%, Voltage Rating=50V
R27: library part CMP-0001-00003-2, "Precision resistor, SMD 0.1 Ohm 0.33 W  ±  1 % 1206, ERJ8BSFR10V, Panasonic Automotive & Industrial Systems", Case Code (Imperial)=1206, Case Code (Metric)=3216, Max Operating Temperature=125°C, Max Power Dissipation=500mW, Min Operating Temperature=-55°C, Package Quantity=5000, Power Rating=330mW, Resistance=0.1, Temperature Coefficient=250ppm/°C, Tolerance=1%
R28: library part CMP-0001-00002-5, "RES SMD 4.42K OHM 1% 1/16W 0402", Case Code (Imperial)=0402, Case Code (Metric)=1005, Max Operating Temperature=155°C, Max Power Dissipation=63mW, Min Operating Temperature=-55°C, Power Rating=62.5mW, Resistance=4.42k, Temperature Coefficient=100ppm/°C, Tolerance=1%, Voltage Rating=50V
SW1: library part CMP-ROOT-00014-1, "100 Series DPDT On-None-On Through Hole Miniature Toggle Switch", Case/Package=dip, Current Rating=5A, Max Operating Temperature=85°C, Min Operating Temperature=-30°C, Package Quantity=200, Voltage Rating (AC)=120V, Voltage Rating (DC)=28V
SW2 SW4: library part CMP-ROOT-00012-1, "BOURNS - PEC11R-4215F-S0024 - Rotary Encoder, Mechanical, Incremental, 24 PPR, 24 Detents, Vertical, With Momentary Push Switch", Case/Package=encoder, Max Operating Temperature=70°C, Min Operating Temperature=-30°C, Package Quantity=150
SW3 SW5 SW6 SW7: library part CMP-ROOT-00013-1, "SWITCH TACTILE SPST-NO 0.05A 12V", Case/Package=SMD/SMT, Color=Black, Contact Resistance=100mR, Current Rating=50mA, Max Operating Temperature=60°C, Max Voltage Rating (DC)=12V, Min Operating Temperature=-20°C, Operating Force=160gf, Package Quantity=1
U1: library part CMP-00001-4, "IC MCU 32BIT 128KB FLASH 100TQFP", Case/Package=TQFP, Frequency=67MHz, Max Operating Temperature=85°C, Max Supply Voltage=5.5V, Min Operating Temperature=-40°C, Min Supply Voltage=1.71V, Package Quantity=1
U2: library part CMP-006-0003-2, "BATTERY CHARGER, 500mA, SOT23-5; Battery Type:Li-Ion, Li-Pol; Input Voltage:6V; Battery Charge Voltage:4.2V; Charge Current Max:500mA; Battery IC Case Style:SOT-23; No. of Pins:5; No. of Series Cells:1; Operating Temperature Max:85 C", Case/Package=SOT-23, Max Charge Current=500mA, Max Input Voltage=6V, Max Operating Temperature=85°C, Max Output Voltage=4.5V, Max Power Dissipation=1.54W, Min Operating Temperature=-40°C, Min Output Voltage=4.168V, Min Supply Voltage=3.75V, Output Current=10mA, Output Voltage=4.2V, Package Quantity=3000
U3: library part CMP-00004-1, "300mA Low-Dropout (LDO) Regulator 5-SOT-23 -40 to 125", Case/Package=SOT-23-5, Dropout Voltage=270mV, Max Input Voltage=5.5V, Max Operating Temperature=125°C, Min Operating Temperature=-40°C, Min Output Voltage=3.3V, Output Current=300mA, Power Supply Rejection Ratio (PSRR)=28dB, Quiescent Current=60uA
U4: library part CMP-00003-1, "Digital Isolator CMOS 4-CH 12Mbps 16-Pin SOIC T/R", Case/Package=SOIC, Isolated Power=No, Max Operating Temperature=105°C, Max Supply Voltage=5.5V, Min Operating Temperature=-40°C, Min Supply Voltage=3.1V, Nominal Supply Current=6mA, Package Quantity=1000
U5: library part CMP-00005-1, "IC REG LIN POS ADJ 1.1A SOT223-3", Case/Package=SOT-223, Dropout Voltage=1.35V, Max Input Voltage=36V, Max Operating Temperature=125°C, Min Current Limit=1.1A, Min Input Voltage=1.2V, Min Operating Temperature=-40°C, Operating Supply Current=300uA, Output Voltage Accuracy=1%, Package Quantity=1, Quiescent Current=500uA

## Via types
v1: diameter 59.06, hole 39.37, Top Layer to Bottom Layer, 110 vias
v2: diameter 19.68, hole 15.75, Top Layer to Bottom Layer, 12 vias
v3: diameter 19.68, hole 15.75, Top Layer to Bottom Layer, tented top, 6 vias
v4: diameter 19.68, hole 15.75, Top Layer to Bottom Layer, tented both sides, 6 vias
v5: diameter 137.8, hole 118.11, Top Layer to Bottom Layer, 4 vias

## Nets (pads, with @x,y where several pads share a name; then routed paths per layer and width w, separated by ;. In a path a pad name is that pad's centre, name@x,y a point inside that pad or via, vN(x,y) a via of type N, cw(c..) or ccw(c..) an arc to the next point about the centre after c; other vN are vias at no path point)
3V3: *1_pta_I1.6 *1_pta_I2.6 *1_pta_I3.6 *2.6 C1.2 C2.2 C3.2 C4.2 C5.2 C6.2 C7.2 C8.2 C9.2 C10.2 C38.2 CN2.5 Display.22 IC2.8 U1.26 U1.37 U1.50 U1.65 U1.75 U1.88 U1.100 U3.5 | length 13295.6
  Top Layer w10: 692.47,1898.73 711.81,1879.39 U1.100@783.03,1879.39 ; 783.03,1944.05 U1.100@783.03,1879.39 ; 854.39,1768.37 783.1,1839.65 783.1,1879.31 U1.100@783.03,1879.39 ; 971.29,1359.46 971.56,1359.74 979.84,1359.74 ; 979.87,1191.79 999.25,1211.16 U1.37@999.25,1280.96 ; C2.2@993.65,1972.14 993.65,1970.17 1007.89,1955.93 1007.89,1945.89 1019.08,1934.7 U1.88@1019.08,1879.41 ; U1.37@999.56,1280.96 999.56,1340.02 ; 1019.25,1768.37 U1.88@1019.25,1879.39 ; 1242.57,1639.1 1262.12,1619.55 U1.65@1318.46,1619.55 1394.33,1619.55 1410.87,1603 ; U1.50@1255.47,1280.96 1311.22,1280.96 ; 1255.86,1816.4 U1.75@1318.46,1816.4 ; 1311.22,1203.21 1311.22,1280.96 ; 1404.98,1280.96 1311.22,1280.96
  Top Layer w20: v1(544.76,1011.59) 552.23,1019.06 572.15,1019.06 644.37,1091.28 644.37,1176.94 v1(638.92,1182.39) ; v1(557,1664) 557,1664.56 v1@565.14,1672.7 ; C4.2@618.29,1629.39 616.32,1629.39 573.01,1672.7 v1@565.14,1672.7 ; IC2.8@666.57,2737.89 743.23,2737.89 775.74,2770.41 854.41,2770.41 880.2,2744.61 880.2,2708.14 809.6,2637.54 *1_pta_I1.6@809.6,2598.43 889.19,2598.43 930.5,2639.74 1215.72,2639.74 1273.77,2581.69 *2.6@1281.64,2581.69 1324.11,2581.69 1391.89,2513.91 1391.89,2308.92 ; 690.95,1898.73 C8.2@624.68,1898.73 624.05,1898.1 600.81,1898.1 554.47,1851.76 554.47,1682.04 563.82,1672.7 v1@565.14,1672.7 ; C9.2@781.44,1981.98 781.44,1945.64 783.03,1944.05 ; 804.21,2383.33 804.21,2375.45 811.02,2368.64 *1_pta_I2.6@818.9,2368.64 819.17,2368.92 882.06,2368.92 926.88,2324.11 926.88,2285.36 1003.18,2209.06 1341.79,2209.06 1391.89,2259.15 1391.89,2308.92 ; 854.39,1768.37 1019.25,1768.37 1207.82,1768.37 ; v1(879.75,1041.09) 819.77,1041.09 774.47,1086.39 774.47,1127 775.15,1127.68 775.15,1297.72 772.39,1300.48 772.39,1317.05 814.8,1359.46 971.29,1359.46 ; C10.2@949.68,1972.14 C2.2@993.65,1972.14 ; 979.84,1359.74 999.56,1340.02 ; 979.87,1191.79 C1.2@979.87,1141.73 979.87,1097.66 995.39,1082.14 C7.2@995.39,1080.18 ; v1(1037.18,823.06) 1171.98,957.86 1187.64,957.86 1315.03,1085.25 1315.03,1199.41 1311.22,1203.21 ; v1(1103.89,708.26) 1114.46,708.26 1143.17,736.97 1163.23,736.97 1196.85,703.35 C38.2@1200.79,703.35 1218.53,721.08 U3.5@1281.5,721.08 ; 1242.57,1639.1 1207.82,1673.84 1207.82,1768.37 ; 1255.86,1816.4 1207.82,1768.37 ; 1404.98,1280.96 1424.9,1261.04 C3.2@1426.87,1261.04 ; 1407.33,1599.47 1427.41,1579.39 C5.2@1463.63,1579.39 ; v1(2349.01,1457.89) 2285.41,1457.89 1997.2,1746.1 1997.2,1811.66 1499.95,2308.92 1391.89,2308.92 ; v1(2750,1481.95) 2794.45,1526.4 2837.76,1526.4 2839.57,1528.21 *1_pta_I3.6@2839.57,1536.08
  Bottom Layer w20: Display.22@177.17,606.69 177.17,615.38 537.29,975.5 537.29,1004.12 v1(544.76,1011.59) ; v1(557,1664) 638.92,1582.08 v1(638.92,1182.39) 797.88,1023.43 879.75,1023.43 v1@888.58,1032.26 ; v1(879.75,1041.09) v1@888.58,1032.26 ; v1(1037.18,823.06) 1037.18,1029.52 1006.09,1060.62 957.97,1060.62 939.28,1041.93 897.79,1041.93 888.58,1032.72 v1@888.58,1032.26 ; CN2.5@2698.43,65.55 2259.42,504.56 2259.42,584.38 2135.54,708.26 v1(1103.89,708.26) 1096.42,715.73 1096.42,751.46 1058.89,788.99 1058.89,790.54 1037,812.43 1037,823 1151.73,823 1786.62,1457.89 v1(2349.01,1457.89) 2715.37,1457.89 2739.43,1481.95 v1(2750,1481.95)
BOOSTER_VCC: C36.1 D2.2 D3.2 IC1.23 | length 2803.1
  Top Layer w15: 2534.33,2278.31 2565.64,2278.31 2582.09,2261.87 2590.59,2261.87 2639.76,2212.69 IC1.23@2639.76,2122.05
  Top Layer w20: v1(2266.15,1889.28) 2269.6,1885.83 2280.91,1885.83 2316.35,1850.4 2358.96,1850.4 ; v1@2280.91,1889.28 2269.69,1900.51 2256.83,1900.51 2178.92,1978.42 2178.92,1980.32 2040.67,2118.57 2040.67,2259.69 2109.84,2328.85 2422.58,2328.85 2444.29,2307.15 2468.55,2283.89 2474.59,2278.31 2534.33,2278.31 ; C36.1@2337.55,1784.45 2351.17,1798.08 2351.17,1826.05 2358.96,1833.83 2358.96,1850.4 ; D2.2@2364.09,1895.68 2358.96,1890.55 2358.96,1850.4 ; D3.2@2985.88,1895.68 3002.61,1895.68 3047.89,1850.4 v1(3092.52,1850.4)
  Bottom Layer w20: v1(2266.15,1889.28) 2270.62,1884.81 2270.62,1676.77 2385.14,1562.25 2597.32,1562.25 2885.46,1850.4 v1(3092.52,1850.4)
GND: *1_pta_I1.2 *1_pta_I2.2 *1_pta_I3.2 C1.1 C2.1 C3.1 C4.1 C5.1 C6.1 C7.1 C8.1 C9.1 C10.1 C11.1 C12.1 C27.2 C30.1 C31.1 C34.1 C35.1 C36.2 C37.1 C38.1 C39_pta_I1.1 C39_pta_I2.1 C39_pta_I3.1 C40_pta_I1.1 C40_pta_I2.1 C40_pta_I3.1 C41_pta_I1.1 C41_pta_I2.1 C41_pta_I3.1 CN2.4 Display.21 IC1.10 IC1.13 IC1.14 IC2.5 IC2.6 R8.1 R10.1 R14.1 R18.1 R19.2 R30.1 SW2.2 SW2.4 SW2.6 SW2.7 SW3.3 SW4.2 SW4.4 SW4.6 SW4.7 SW5.3 SW6.3 SW7.3 U1.10 U1.12 U1.13 U1.14 U1.38 U1.64 U1.66 U1.87 U3.2 | length 21346.2
  Top Layer w10: 650.98,1566.35 656.83,1560.49 U1.14@720.03,1560.49 ; 650.98,1580.18 U1.13@720.03,1580.18 ; 656.83,1599.86 U1.12@720.03,1599.86 784.45,1599.86 ; 662.69,1639.23 U1.10@720.03,1639.23 ; U1.38@1019.25,1280.96 U1.38@1019.25,1316.89 ; 1024.06,1350.16 1024.06,1329.87 1019.59,1325.4 1019.59,1317.23 U1.38@1019.25,1316.89 ; C2.1@1038.58,1972.11 1038.58,1915.66 1038.93,1915.31 U1.87@1038.93,1879.39 ; 1046.8,1192.38 1019.25,1219.94 U1.38@1019.25,1316.89 ; 1225.62,1575.47 1250,1599.86 U1.64@1318.46,1599.86 1372.29,1599.86 1382.83,1589.32 1425.44,1546.71 1474.69,1546.71 1477.24,1549.26 ; U1.66@1318.46,1639.23 1421.82,1639.23 1436.66,1624.39 1458,1624.39 C5.1@1463.63,1618.76
  Top Layer w15: IC1.10@2742.13,1893.7 2742.13,1819.39 2765.84,1795.67 2793.7,1795.67 2811.74,1777.64 2874.93,1777.64 2888.78,1763.79 2888.78,1721.26 2881.28,1713.77 2856.65,1713.77 C35.1@2853.52,1710.64 ; IC1.13@2818.9,1893.7 IC1.14@2844.49,1893.7 2893.43,1893.7 2936.73,1850.4
  Top Layer w20: C39_pta_I1.1@416.34,2507.87 418.31,2509.84 C40_pta_I1.1@511.81,2509.84 ; C39_pta_I2.1@442.87,2282.03 501.18,2282.03 ; v1(455.67,2705.72) 460.93,2700.45 477.5,2700.45 514.95,2737.89 IC2.5@586.3,2737.89 IC2.6@608.38,2737.89 ; v1(505.91,2459.24) 509.85,2463.17 509.85,2507.87 C40_pta_I1.1@511.81,2509.84 ; v1(527.75,2229.05) 503.39,2229.05 v1@501.18,2231.25 ; C8.1@624.68,1859.36 624.05,1858.73 622.08,1858.73 583.97,1820.61 583.97,1707.69 613.77,1677.89 620.59,1677.89 650.38,1648.1 650.38,1639.82 656.83,1633.37 ; 650.98,1566.35 650.98,1580.18 ; 662.69,1639.23 656.83,1633.37 ; *1_pta_I1.2@701.33,2561.02 699.52,2559.21 670.98,2559.21 627.16,2515.39 609.07,2515.39 606.97,2513.29 515.26,2513.29 C40_pta_I1.1@513.78,2511.81 C40_pta_I1.1@511.81,2509.84 ; *1_pta_I2.2@710.63,2331.24 708.82,2329.43 693.51,2329.43 689.23,2325.15 682.87,2325.15 666.33,2308.61 666.33,2305.96 649.79,2289.42 640.32,2289.42 631.08,2280.18 C41_pta_I2.1@629.11,2280.18 628.19,2281.1 537.35,2281.1 C40_pta_I2.1@536.42,2282.03 501.18,2282.03 ; C6.1@735.78,1160.91 735.78,1059.34 803.06,992.06 900.06,992.06 919.59,1011.59 v1(985.78,1011.59) ; 784.45,1599.86 1019.25,1599.86 1054.44,1564.67 1120.5,1498.6 1123.69,1495.41 1027.6,1399.31 1027.6,1377.45 ; v1(940.63,3592.52) 945.55,3597.44 1009.77,3597.44 SW4.2@1014.69,3602.36 1140.67,3728.35 1214.25,3728.35 ; v1@985.78,1007.68 1034.76,1056.65 C7.1@1034.76,1080.18 1034.76,1129.68 C1.1@1046.8,1141.73 1046.8,1192.38 ; 1027.6,1353.7 1027.6,1377.45 ; C2.1@1033.02,1972.14 1028.18,1976.98 1028.18,1991.74 1008.24,2011.69 1008.24,2032.86 C12.1@989.62,2051.48 989.62,2047.55 947.52,2005.45 922.66,2005.45 910.94,1993.74 910.94,1972.77 C10.1@910.31,1972.14 910.31,1981.98 C9.1@820.81,1981.98 820.81,2006.03 795.05,2031.8 675.47,2031.8 630.37,1986.7 ; C38.1@1200.79,636.42 1200.79,581.73 v1@1237.3,545.22 ; v1(1224.22,543.15) 1235.24,543.15 v1@1237.3,545.22 ; 1225.62,1575.47 1027.6,1377.45 ; SW4.6@1290.28,3279.53 1214.25,3279.53 1208.4,3285.39 1208.4,3722.49 1214.25,3728.35 ; SW4.7@1290.28,3728.35 1214.25,3728.35 ; SW4.7@1306.02,3728.35 1526.03,3508.35 SW4.4@1581.14,3508.35 ; U3.2@1318.9,630.49 1318.9,520.31 C37.1@1307.29,508.7 1273.82,508.7 v1@1237.3,545.22 ; C3.1@1426.87,1221.67 1560.53,1221.67 1606.99,1268.13 1606.99,1547.68 ; 1429.33,1549.89 1429.96,1549.26 1477.24,1549.26 1484.31,1549.26 1486.14,1551.09 1498.57,1551.09 C11.1@1521.75,1574.27 ; C5.1@1467.5,1616.86 1471.23,1613.13 1482.89,1613.13 C11.1@1521.75,1574.27 ; C11.1@1525.69,1574.27 C11.1@1521.75,1574.27 ; C11.1@1528.02,1571.93 1582.74,1571.93 1606.99,1547.68 ; v1(1658.52,1547.68) 1606.99,1547.68 ; R19.2@1821.06,461.86 1889.71,461.86 1923.33,428.24 1998.71,428.24 1999.01,428.55 2217.14,428.55 2257.92,387.77 v1(2260.55,387.77) ; R30.1@1871.01,2044.59 1872.98,2044.59 v1(1917.56,2000.01) 2133.12,1784.45 ; SW2.2@2048.55,3602.37 2174.53,3728.35 SW2.7@2324.14,3728.35 2400.16,3728.35 2447.18,3681.34 2447.18,3462.84 ; v1(2128.4,2187.43) 2129.57,2187.43 2130.03,2187.89 2130.03,2198.46 2158.61,2227.04 2158.61,2268.9 C31.1@2159.24,2269.53 ; C36.2@2270.62,1784.45 2133.12,1784.45 ; SW2.6@2324.14,3279.53 2324.14,3339.81 2447.18,3462.84 ; C27.2@2503.94,1697.1 2501.97,1697.1 2434.82,1629.95 2434.82,1613.64 ; R8.1@2565.93,1608.13 2563.14,1605.33 2561.17,1605.33 2518.09,1562.25 2463.54,1562.25 2434.82,1590.97 2434.82,1613.64 ; R8.1@2566.07,1608.27 2599.32,1608.27 ; R14.1@2600.8,1709.65 2600.8,1707.45 2600.2,1706.85 2600.2,1609.15 2599.32,1608.27 ; R14.1@2600.8,1709.65 2652.93,1709.67 2654.95,1709.67 2672.7,1691.93 C34.1@2707.22,1691.93 2707.85,1691.3 2711.08,1691.3 2711.43,1690.95 C30.1@2753.66,1690.95 ; v1(2685.11,3543.9) 2659.37,3543.9 SW2.4@2619.42,3503.94 2488.27,3503.94 2447.18,3462.84 ; C35.1@2853.52,1710.64 2851.55,1710.64 2850.92,1710.01 2850.92,1689.94 2791.74,1630.77 2725.49,1630.77 2702.01,1607.29 R18.1@2664.01,1607.29 ; *1_pta_I3.2@2876.97,1427.81 2875.16,1429.62 2875.16,1451.3 2859.46,1467 2811.61,1467 2777.53,1432.92 2729.69,1432.92 2664.01,1498.6 R18.1@2664.01,1607.29 ; *1_pta_I3.2@2878.78,1426 2878.78,1410.69 2883.06,1406.41 2883.06,1400.05 2899.66,1383.45 2913.52,1383.45 2930.12,1366.85 C41_pta_I3.1@2930.12,1342.52 ; C41_pta_I3.1@2930.12,1340.55 C40_pta_I3.1@2930.12,1234.9 2930.64,1234.38 2930.64,1134.04 C39_pta_I3.1@2931.16,1133.52 ; C41_pta_I3.1@2930.12,1340.55 C41_pta_I3.1@2930.12,1342.52 ; 2936.73,1850.4 2969.88,1850.4 3035.17,1785.1 3179.1,1785.1 3179.1,1591.5 C41_pta_I3.1@2930.12,1342.52 ; v1@501.18,2231.25 501.18,2115.88 630.37,1986.7 ; v1@501.18,2231.25 501.18,2282.03 ; 630.37,1986.7 630.37,1969.38 504.6,1843.61 504.6,1630.65 521.65,1613.61 527.7,1607.55 569.33,1607.55 586.86,1590.02 C4.1@618.29,1590.02 623.91,1584.39 644.73,1584.39 648.94,1580.18 650.98,1580.18 ; 650.98,1580.18 650.98,1594 656.83,1599.86 656.83,1633.37 ; 2133.12,1784.45 2133.12,1680.97 2200.45,1613.64 2434.82,1613.64 ; 2599.32,1608.27 2618.26,1608.27 2619.24,1607.29 R18.1@2664.01,1607.29
  Bottom Layer w20: v1(527.75,2229.05) 527.75,2426.83 505.91,2448.67 v1(505.91,2459.24) 455.67,2509.48 v1(455.67,2705.72) 455.67,3093.65 864,3501.99 SW7.3@864,3592.52 v1(940.63,3592.52) 945.55,3597.44 1009.77,3597.44 SW4.2@1014.69,3602.36 1140.67,3728.35 SW4.7@1290.28,3728.35 ; v1(985.78,1011.59) 985.78,805.13 1003.43,787.48 1003.43,739.39 1097.81,645 1122.36,645 v1(1224.22,543.15) 1687.36,543.15 1719.8,575.59 1889.71,575.59 1942.67,628.54 2173.54,628.54 2185.25,616.83 2185.25,514.07 2198.09,501.23 2198.09,460.79 2260.55,398.34 v1(2260.55,387.77) ; SW4.6@1290.28,3279.53 SW4.7@1290.28,3728.35 ; SW4.7@1306.02,3728.35 SW4.7@1290.28,3728.35 ; SW4.4@1581.14,3508.35 SW4.4@1585.55,3503.94 1745.6,3503.94 1844.02,3602.37 SW2.2@2048.55,3602.37 2182.41,3602.37 2308.39,3728.35 SW2.7@2324.14,3728.35 2920.65,3728.35 2950,3699 2950,3656.3 SW3.3@2994.09,3612.21 2998.49,3607.81 3053.61,3607.81 3090.55,3570.87 3090.55,3369.88 3074.41,3353.74 2935.57,3353.74 2745.42,3543.9 v1(2685.11,3543.9) ; v1(1658.52,1547.68) 1658.52,1557.23 1657.55,1558.19 1657.55,1571.71 1662.63,1576.68 1926.92,1890.29 1926.22,1898.55 v1(1917.56,2000.01) ; v1@1924.21,2006.66 1924.21,2146.36 1965.74,2187.89 2127.93,2187.89 v1(2128.4,2187.43) ; v1@2268.37,390.52 2278.59,380.3 2283.67,380.3 CN2.4@2598.43,65.55
Net*1_pta_I1_1: *1_pta_I1.1 C41_pta_I1.2 R22_pta_I1.2 | length 144.1
  Top Layer w20: R22_pta_I1.2@606.47,2602.36 R22_pta_I1.2@607.46,2601.38 ; C41_pta_I1.2@608.44,2554.13 607.46,2555.12 R22_pta_I1.2@607.46,2601.38 ; *1_pta_I1.1@701.33,2598.43 699.36,2600.39 608.44,2600.39 R22_pta_I1.2@607.46,2601.38
Net*1_pta_I1_3: *1_pta_I1.3 *1_pta_I1.4 *2.1 | length 519.7
  Top Layer w20: *1_pta_I1.3@701.33,2523.62 *1_pta_I1.4@809.6,2523.62 880.8,2523.62 967.42,2610.24 1078.6,2610.24 1106.45,2582.39 1128.9,2582.39 1129.59,2581.69 *2.1@1173.38,2581.69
